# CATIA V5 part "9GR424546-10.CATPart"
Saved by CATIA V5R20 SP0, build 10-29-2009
Part number: 9GR424546-10
Revision: ANY
Definition: UNKNOWN
Nomenclature: 9GR424546-10
Source: Unknown
Bounding box of the stored display mesh (mm): x -22.944 to 23, y -40 to 5, z -23 to 23
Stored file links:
  C:\Users\Utente\Desktop\IO LAVORO\3D X SITO CF\CUMSA\3D files GR\GR 424546-10\9GR424546-10.CATPart
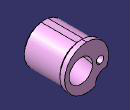
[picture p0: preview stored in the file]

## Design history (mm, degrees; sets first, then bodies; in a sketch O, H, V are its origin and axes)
Body1 "Cortar-Extruir7" (main body)
  Solid1: solid without history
